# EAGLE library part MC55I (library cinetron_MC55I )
GSM modul Cinterion MC55i s konektorem
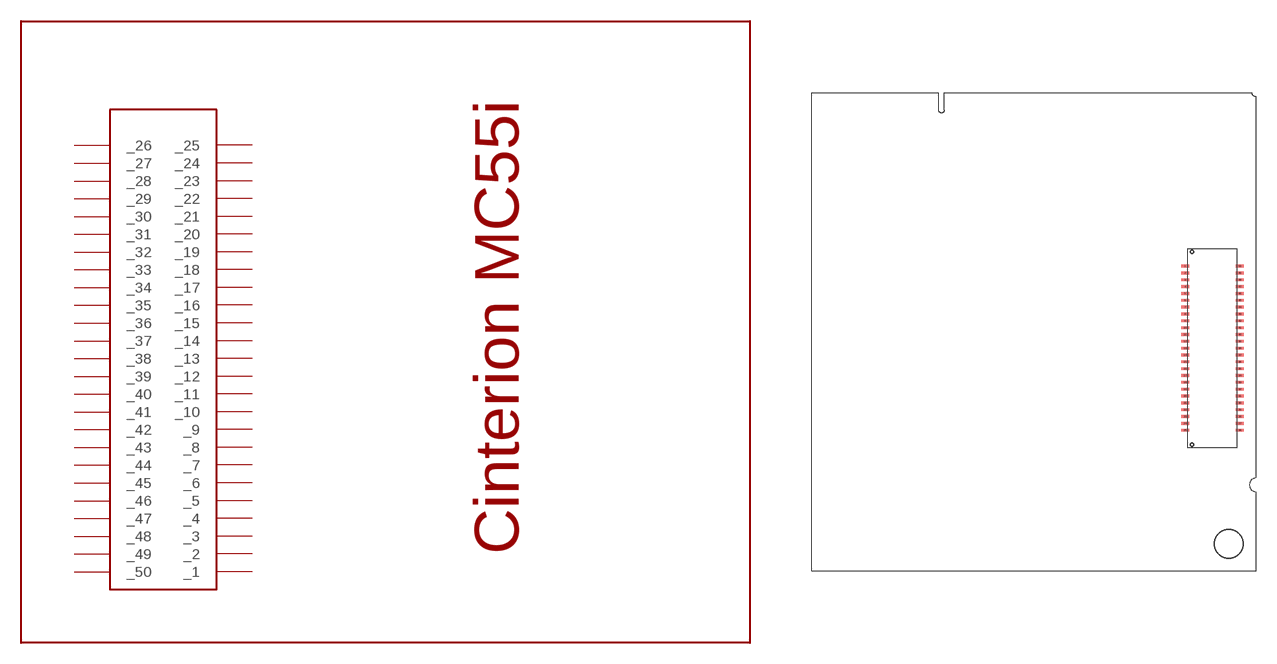
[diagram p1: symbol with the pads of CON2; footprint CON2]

Designator prefix -

## MC55I  [CON2]
1  _26
2  _27
3  _28
4  _29
5  _30
6  _31
7  _32
8  _33
9  _34
10  _35
11  _36
12  _37
13  _38
14  _39
15  _40
16  _41
17  _42
18  _43
19  _44
20  _45
21  _46
22  _47
23  _48
24  _49
25  _50
26  _1
27  _2
28  _3
29  _4
30  _5
31  _6
32  _7
33  _8
34  _9
35  _10
36  _11
37  _12
38  _13
39  _14
40  _15
41  _16
42  _17
43  _18
44  _19
45  _20
46  _21
47  _22
48  _23
49  _24
50  _25

## Footprint CON2 (pad centres in mm)
smd 0.6 x 0.2: 1 13.33,5.79; 2 13.33,5.29; 3 13.33,4.79; 4 13.33,4.29; 5 13.33,3.79; 6 13.33,3.29; 7 13.33,2.79; 8 13.33,2.29; 9 13.33,1.79; 10 13.33,1.29; 11 13.33,0.79; 12 13.33,0.29; 13 13.33,-0.21; 14 13.33,-0.71; 15 13.33,-1.21; 16 13.33,-1.71; 17 13.33,-2.21; 18 13.33,-2.71; 19 13.33,-3.21; 20 13.33,-3.71; 21 13.33,-4.21; 22 13.33,-4.71; 23 13.33,-5.21; 24 13.33,-5.71; 25 13.33,-6.21; 26 17.33,-6.21; 27 17.33,-5.71; 28 17.33,-5.21; 29 17.33,-4.71; 30 17.33,-4.21; 31 17.33,-3.71; 32 17.33,-3.21; 33 17.33,-2.71; 34 17.33,-2.21; 35 17.33,-1.71; 36 17.33,-1.21; 37 17.33,-0.71; 38 17.33,-0.21; 39 17.33,0.29; 40 17.33,0.79; 41 17.33,1.29; 42 17.33,1.79; 43 17.33,2.29; 44 17.33,2.79; 45 17.33,3.29; 46 17.33,3.79; 47 17.33,4.29; 48 17.33,4.79; 49 17.33,5.29; 50 17.33,5.79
